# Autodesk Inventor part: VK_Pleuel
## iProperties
Created: 2004-01
Part Number: VK_Pleuel
Material: Stahl (schweißbar)
Document SubType Name: Modellieren
Designer: Ulrich
Control State: 0
Master: False
Checked Out: False
Shininess: 20.0
Angle Display Precision: 2
Document Length Units: 11269
Document Angle Units: 11279
Document Time Units: 11290
Document Mass Units: 11283
Document Length Units Precision: 3
Document Angle Units Precision: 2
Density: 0.0
Volumn: 0.0
Area: 0.0
PropertySet Name: Model Information
Author: Ulrich
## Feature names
1. Grundform_seitlich [Extrusion]
2. Grundform_oben [Extrusion]
3. Rundung1 [Fillet]
4. Pleuelauge_KW [Hole]
5. Pleuelauge_VK [Hole]
